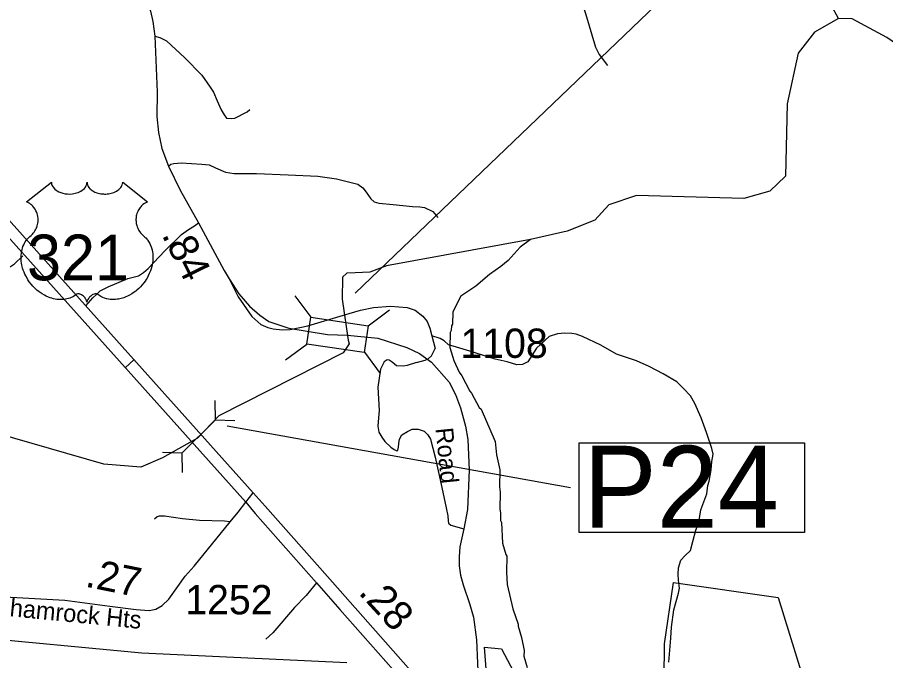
# Model space of a CAD drawing. Extents: x 1159738 to 1321356, y 736314 to 882035.
# Drawn here: x 1275757 to 1279458, y 760767 to 763510 of the extents above; entities that cross this region are included whole.
import ezdxf

# ---------------------------------------------------------------- set-up
doc = ezdxf.new("R2010")
doc.units = 0
for name, color, linetype in [('Exist Boundary Political City Limit New', 7, 'Continuous'), ('Exist Hydrographic Creek Single Shore', 7, 'Continuous'), ('Exist Hydrographic Misc Water Feature', 7, 'Continuous'), ('Exist Road Non-System Type 51', 7, 'Continuous'), ('Exist Road Primary US Divided Attributed', 7, 'Continuous'), ('Exist Road Primary US Mileage Hundredths English Label', 7, 'Continuous'), ('Exist Road Primary US Shield CELL', 7, 'Continuous'), ('Exist Road Primary US Shield Number Label', 7, 'Continuous'), ('Exist Road Primary US Structure Pipe CELL', 7, 'Continuous'), ('Exist Road Primary US Structure Pipe Number Label', 7, 'Continuous'), ('Exist Road Secondary Mileage Hundredths English Label', 7, 'Continuous'), ('Exist Road Secondary Structure Standard Bridge CELL', 7, 'Continuous'), ('Exist Road Secondary Structure Standard Bridge Number Label', 7, 'Continuous'), ('Exist Road Secondary Type 51 Attributed', 7, 'Continuous'), ('Exist Road Secondary Type 51 Label', 7, 'Continuous'), ('Exist Road Secondary Type 51 Number Label', 7, 'Continuous'), ('Map Preparation Boundary City Limit Buffer Line', 7, 'Continuous')]:
    doc.layers.add(name, color=color, linetype=linetype)

msp = doc.modelspace()

# ---------------------------------------------------------------- linework, layer by layer
at = {"layer": 'Exist Boundary Political City Limit New'}
for points in [[(1278511.7, 760540.3), (1278515.7, 760839), (1278554.1, 761100.2), (1278999.4, 761036.8), (1279308.4, 760038.1)], [(1275619.3, 760456.4), (1275534.8, 760871.3), (1276287.6, 760801.1), (1277161.7, 760759.7)], [(1277763.7, 760620.9), (1277747.9, 760824.6), (1277820.8, 760816.9), (1277947.5, 760578.7)]]:
    msp.add_lwpolyline(points, dxfattribs=at)
at = {"layer": 'Exist Hydrographic Creek Single Shore'}
for points in [[(1279256.7, 763505), (1279224.7, 763564.7), (1278896.6, 763787.9), (1278758.6, 763958.1), (1278294.7, 764394.2), (1278259.6, 764444.5), (1278162.6, 764455.9), (1277896.7, 764497.4), (1277500.6, 764682.6), (1277293.6, 764729.4), (1277035.7, 764741.1), (1276514.6, 764912.5), (1276316.7, 765028), (1275935.6, 765462.4), (1275671.6, 765894.4), (1275435.5, 766142.1), (1275229.6, 766238.2), (1275030.6, 766275)], [(1279256.7, 763505), (1279154.7, 763447.9), (1279085.7, 763357.4), (1279038.6, 763141.7), (1279031.6, 762833.3), (1278963.7, 762769), (1278853.7, 762738.3), (1278395.7, 762750.8), (1278277.7, 762710.6), (1278217.7, 762646.1), (1278100.7, 762599.2), (1277943.5, 762563.4), (1277329.6, 762450.6), (1277258.9, 762423.5), (1277196.4, 762421.4), (1277161.3, 762420), (1277143, 762402.4), (1277140.9, 762308.3), (1277166.7, 762134.1)], [(1280098.6, 762815.2), (1280048.7, 762832.6), (1279945.7, 763038.2), (1279815.7, 763181.9), (1279462.7, 763425.3), (1279314.6, 763503.8), (1279256.7, 763505)], [(1276523.9, 761715.6), (1276375.7, 761632.7), (1276282.6, 761591.9), (1276124.6, 761604.9), (1275586.7, 761760.1), (1275554.7, 761826.4), (1275516.6, 762329.5), (1275469.7, 762455.1), (1275027.6, 762756.1), (1274952.6, 762783.9), (1274794.8, 762745.5), (1274683.6, 762681), (1274528.6, 762487.1), (1274390.3, 762149.8), (1274352, 762101.2)], [(1277255.4, 762409), (1277255.4, 762409)], [(1277166.7, 762134.1), (1277170.7, 762117.7), (1277145.7, 762080.1), (1276615.3, 761811.9), (1276523.9, 761715.6)]]:
    msp.add_lwpolyline(points, dxfattribs=at)
at = {"layer": 'Exist Hydrographic Misc Water Feature'}
msp.add_lwpolyline([(1277943.5, 762563.4), (1277900.3, 762530.3), (1277848.7, 762473.8), (1277817.9, 762448.7), (1277769, 762414.1), (1277711.6, 762363.8), (1277646.4, 762321.6), (1277612.6, 762254.6), (1277611.1, 762202.7), (1277606.8, 762194.8), (1277606.3, 762174.8), (1277602.1, 762167), (1277600.4, 762103), (1277616.8, 762046.5), (1277639.4, 761997.9), (1277651, 761981.6), (1277685.2, 761916.6), (1277693, 761908.4), (1277725.3, 761846.3), (1277733, 761839.3), (1277793.2, 761701.5), (1277799.7, 761645.4), (1277813.9, 761581), (1277811.9, 761509.1), (1277815.3, 761485), (1277813.2, 761413.1), (1277816.8, 761396.9), (1277815.9, 761365), (1277819.7, 761356.9), (1277825.2, 761268.7), (1277838.9, 761220.1), (1277843.7, 761212.2), (1277841.8, 761144.3), (1277844.4, 761092.2), (1277869.4, 760987.5), (1277891.7, 760922.9), (1277891.5, 760914.9), (1277906.1, 760866.5), (1277916.6, 760810.2), (1277915.9, 760786.2), (1277930.5, 760737.8)], dxfattribs=at)
at = {"layer": 'Exist Road Non-System Type 51'}
for points in [[(1278073.2, 763861), (1278092.8, 763812.1), (1278132, 763674.8), (1278178.3, 763526.7), (1278221.1, 763383.3), (1278237.1, 763352.5), (1278272.8, 763305.2)], [(1276342.1, 763430), (1276364.5, 763424.4), (1276391.9, 763410.3), (1276469.9, 763337.2), (1276543.6, 763263.6), (1276578, 763213), (1276592.8, 763191.9)], [(1276592.8, 763191.9), (1276608.8, 763154.2), (1276625.6, 763115.5), (1276637.6, 763094.4), (1276648.8, 763081), (1276667.8, 763078.9), (1276683.3, 763081), (1276736, 763107.8), (1276747.2, 763116.9)], [(1276400.5, 762875.2), (1276411.3, 762883.9), (1276423.2, 762887.5), (1276454.8, 762890.3), (1276543.4, 762884.7), (1276574.3, 762881.8), (1276601, 762869.2), (1276643.9, 762850.2), (1276681.1, 762844.6), (1276776.7, 762845.3), (1276910.9, 762838.9), (1277037.4, 762832.6), (1277117.2, 762821.4), (1277208.5, 762798.9), (1277229.6, 762784.1), (1277243.7, 762765.1), (1277263.3, 762736.3), (1277277.4, 762723.7), (1277297.1, 762718.7), (1277358.2, 762713.1), (1277440.8, 762703.4), (1277471.7, 762702.7), (1277492.1, 762699.2), (1277527.9, 762682.4), (1277549, 762657)], [(1275429.3, 762666.4), (1275448.3, 762635.4), (1275482.7, 762601.7), (1275519.2, 762570.7), (1275556.5, 762552.5), (1275598.6, 762520.1), (1275635.2, 762487.1), (1275659.1, 762463.1), (1275681.5, 762447), (1275698.4, 762441.3), (1275713.9, 762442.8), (1275727.9, 762448.4), (1275744.8, 762459.6), (1275780.6, 762494.1)], [(1276048.4, 762280), (1276078.6, 762314.5), (1276094.1, 762329.3), (1276110.2, 762344.7), (1276143.3, 762360.9), (1276226.9, 762396.8), (1276273.3, 762408.7), (1276293.6, 762422.1), (1276314.7, 762439.7), (1276385, 762514.2), (1276456.5, 762584.1), (1276486.7, 762605.9), (1276511.3, 762621.3), (1276528.9, 762634.7)], [(1276659.3, 762395.2), (1276698, 762318.6), (1276755.5, 762235.1), (1276794.2, 762201.3), (1276824.4, 762188), (1276847.6, 762181.7), (1276886.2, 762177.4), (1276919.3, 762179.5), (1276994.4, 762195.4), (1277147.2, 762240.8)], [(1277147.2, 762240.8), (1277218.9, 762262.4), (1277275.1, 762273), (1277347.5, 762279.3), (1277417.7, 762273.7), (1277452.6, 762261.9), (1277485, 762236.6), (1277503.2, 762214.1), (1277514.5, 762185.3), (1277523.5, 762153), (1277537.4, 762099)], [(1278534.3, 760760.5), (1278541.6, 760863.3), (1278545.6, 760909.9), (1278555.6, 760984), (1278575.6, 761055.6), (1278579.6, 761076.9), (1278574.9, 761110.9), (1278572.9, 761136.3), (1278574.2, 761163), (1278584.9, 761195), (1278602.9, 761215.2), (1278626.2, 761236.5), (1278635.6, 761275.2), (1278648.9, 761323.2), (1278661.6, 761355.9), (1278670.2, 761410.6), (1278696.2, 761479), (1278700.2, 761513.7), (1278706.2, 761533), (1278713.5, 761580.4), (1278717.5, 761616.4), (1278722.2, 761648.4), (1278716.8, 761671.9), (1278694.8, 761739.9), (1278672.2, 761802.6), (1278644.2, 761863.3), (1278626.2, 761896.7), (1278595.5, 761928), (1278568.2, 761956), (1278509.8, 761991), (1278449.8, 762021.7), (1278395.2, 762045.7), (1278309.9, 762073.7), (1278243.2, 762112.4), (1278165.2, 762149.8), (1278138.8, 762158.9), (1278120.2, 762162.9), (1278090.8, 762164.2), (1278059.5, 762160.2), (1278023.5, 762150.2), (1277970.2, 762099.5), (1277932.4, 762040.9), (1277910.4, 762029.6), (1277885.1, 762028.2), (1277844.4, 762040.9), (1277792.7, 762052.9), (1277685.8, 762086.9), (1277628, 762104.2), (1277594.1, 762113.6), (1277576.1, 762130.9), (1277559.4, 762141.6), (1277523.5, 762153)], [(1277458.3, 762039.2), (1277494.8, 762048), (1277508.2, 762054.2), (1277521.6, 762067.6), (1277537.4, 762099)], [(1276216.5, 762015.3), (1276254.4, 762051.9)], [(1277458.3, 762039.2), (1277417.6, 762026.3), (1277403.1, 762023.2), (1277372.2, 762024.3), (1277353.7, 762039.7), (1277341.3, 762049), (1277333.1, 762050), (1277319.7, 762041.8), (1277304.2, 762010.9), (1277293.2, 761933.9)], [(1277293.2, 761933.9), (1277298.8, 761833.4), (1277296.1, 761803), (1277292.6, 761766.5), (1277297.5, 761741.2), (1277310.1, 761720.1), (1277322.8, 761701.1), (1277348.8, 761677.9), (1277362.8, 761667.3), (1277374.8, 761661.7), (1277379, 761664.5), (1277381.1, 761677.2), (1277382.5, 761692.6), (1277386, 761711.6), (1277395.9, 761729.9), (1277419.1, 761744.7), (1277439.4, 761753.8), (1277465.4, 761753.8), (1277491.4, 761746.1), (1277506.9, 761730.6), (1277517.4, 761711.6), (1277537.8, 761635), (1277565.9, 761504.9), (1277584.7, 761418.7), (1277591, 761384.9), (1277593.1, 761363.1), (1277593.9, 761354), (1277605.1, 761345.5), (1277659.9, 761330)], [(1276663.2, 761359.5), (1276639, 761361.5), (1276533.4, 761365.3), (1276460.7, 761372.1), (1276384.2, 761383.8), (1276361, 761383.8), (1276353.2, 761380.8), (1276341.6, 761370.2)], [(1277031.5, 761099.6), (1277006.2, 761067.9), (1276987.9, 761045.4), (1276938, 760993.4), (1276846, 760886.5), (1276816.4, 760859.1)]]:
    msp.add_lwpolyline(points, dxfattribs=at)
at = {"layer": 'Exist Road Primary US Divided Attributed'}
for points in [[(1276761.9, 761482.7), (1274721, 763763.6), (1274480.5, 764027.9), (1274341.6, 764181.8), (1274336.1, 764187.9), (1274158.2, 764387.1), (1273955.8, 764610.5), (1273937.2, 764629.8), (1273665.3, 764929.8), (1273491.1, 765126.5), (1273244.4, 765402.2), (1272934.1, 765748.5), (1272883, 765805.3), (1272660.8, 766051.7), (1272348.9, 766398.3), (1272213.6, 766549.1), (1272116.1, 766659.4), (1272031.2, 766754.1), (1271838.3, 766967.2), (1271569.7, 767262), (1271493.2, 767352.1), (1271065.1, 767830.6)], [(1271023.6, 767793.5), (1271459.7, 767322.4), (1271535.9, 767232.7), (1271794.5, 766934.6), (1271824.4, 766899.2), (1271959.1, 766752.4), (1272182.4, 766504.4), (1272240.1, 766441.4), (1272337.9, 766331.1), (1273164.5, 765409.1), (1273205.2, 765363.3), (1273370.7, 765181.3), (1273442.3, 765099.1), (1273663.8, 764841.4), (1273741.2, 764755.3), (1273926.3, 764563.6), (1274002.6, 764479.8), (1274119.3, 764350.9), (1274294.4, 764154.2), (1274358, 764082.6), (1274673.3, 763740.4), (1276730.3, 761442.6)], [(1277736.2, 760394.7), (1277655.5, 760474.7), (1277476.4, 760675.6), (1277079.1, 761125.6), (1276813.1, 761426), (1276761.9, 761482.7)], [(1276730.3, 761442.6), (1276770.9, 761394.3), (1277031.5, 761099.6), (1277131.8, 760985.7), (1277392.8, 760689.7), (1277491.2, 760578.6), (1277689.2, 760354.6), (1277747.5, 760296.9)]]:
    msp.add_lwpolyline(points, dxfattribs=at)
at = {"layer": 'Exist Road Primary US Shield CELL'}
msp.add_lwpolyline([(1275901.5, 762807.8), (1275901.7, 762803.4), (1275902.8, 762798.2), (1275903.6, 762795.5), (1275906.1, 762790.4), (1275910.1, 762784.3), (1275915.7, 762778.3), (1275922, 762773.1), (1275926.3, 762770.3), (1275933.6, 762766.4), (1275941.8, 762763), (1275950.9, 762760.3), (1275960.3, 762758.5), (1275970.5, 762757.3), (1275980.6, 762757.1), (1275991.6, 762758), (1276003.6, 762760.3), (1276009.2, 762761.7), (1276015.4, 762763.9), (1276021.2, 762766.2), (1276027.5, 762769.6), (1276032.6, 762772.9), (1276036.6, 762775.8), (1276042.2, 762781.2), (1276046.7, 762786.8), (1276048.6, 762789.9), (1276050.2, 762792.9), (1276052.5, 762799.3), (1276053.1, 762802.2), (1276053.5, 762808.1), (1276053.9, 762803.1), (1276054.4, 762800), (1276055.2, 762797), (1276056.5, 762793.8), (1276058.8, 762789.3), (1276061.3, 762785.5), (1276066, 762779.9), (1276069, 762777.2), (1276071.6, 762775), (1276078.9, 762770), (1276087.3, 762765.7), (1276091.5, 762763.9), (1276095.7, 762762.4), (1276101.1, 762760.8), (1276106.7, 762759.5), (1276112.2, 762758.5), (1276117.9, 762757.7), (1276123.7, 762757.3), (1276128.4, 762757.1), (1276134.1, 762757.2), (1276139.5, 762757.5), (1276144.9, 762758.1), (1276151, 762759.2), (1276155.8, 762760.2), (1276162.2, 762761.9), (1276168, 762764), (1276173.1, 762766.2), (1276179.6, 762769.6), (1276185, 762773), (1276188.9, 762776.1), (1276193.5, 762780.4), (1276197.9, 762785.5), (1276200.5, 762789.2), (1276202.3, 762793), (1276204, 762797), (1276205, 762801.3), (1276205.5, 762805), (1276205.6, 762808.2), (1276311.9, 762723.5), (1276309.4, 762722.5), (1276303.6, 762719.7), (1276299.1, 762717), (1276291.7, 762711.9), (1276288.6, 762709), (1276285.5, 762706.1), (1276282.6, 762702.9), (1276280, 762700), (1276277, 762695.7), (1276274.2, 762691.5), (1276271.5, 762686.7), (1276269.5, 762682.7), (1276266.3, 762674.1), (1276264.7, 762668.7), (1276263.7, 762664.1), (1276262.4, 762654.7), (1276262.1, 762650.1), (1276262.1, 762645.7), (1276262.4, 762641), (1276262.8, 762636.4), (1276263.6, 762631.7), (1276264.4, 762627.6), (1276265.7, 762622.5), (1276267.6, 762616.6), (1276269.9, 762610.9), (1276274.8, 762601.7), (1276281, 762592.2), (1276285.5, 762587), (1276289.9, 762582.4), (1276296.4, 762576.9), (1276300, 762573.8), (1276304, 762569.7), (1276310.7, 762562), (1276313.4, 762558.3), (1276316.1, 762554.2), (1276318.6, 762550), (1276321.1, 762545.5), (1276323.2, 762541.6), (1276326.9, 762532.4), (1276329.6, 762523.6), (1276330.9, 762518.9), (1276332.9, 762508.5), (1276333.6, 762503.4), (1276334.4, 762493.2), (1276334.5, 762480.9), (1276333.5, 762469.2), (1276331.3, 762455.6), (1276329.5, 762447.4), (1276326.7, 762437.9), (1276324, 762429.7), (1276319.1, 762417.6), (1276314.8, 762408.8), (1276309.3, 762398.5), (1276305.4, 762392.3), (1276301, 762385.6), (1276295.4, 762378), (1276288.9, 762369.8), (1276281, 762361.2), (1276274.7, 762354.9), (1276266.4, 762347.4), (1276261.4, 762343.3), (1276254.2, 762337.9), (1276244.4, 762331.4), (1276234.7, 762325.8), (1276226.5, 762321.6), (1276219.2, 762318.4), (1276209.8, 762314.8), (1276194.1, 762310.5), (1276188.4, 762309.3), (1276181.7, 762308.3), (1276175.3, 762307.7), (1276169.2, 762307.3), (1276160.9, 762307.3), (1276152.7, 762307.9), (1276144.9, 762309.1), (1276136.8, 762310.8), (1276128.3, 762313.3), (1276120.6, 762316.3), (1276112.8, 762320.1), (1276099.7, 762328.4), (1276095.9, 762330.4), (1276093.7, 762331), (1276088.7, 762331.2), (1276083.9, 762330.2), (1276079, 762328.3), (1276076, 762326.7), (1276072.1, 762324.1), (1276069.1, 762321.8), (1276065.5, 762318.3), (1276063, 762315.4), (1276061, 762313.2), (1276057.3, 762307.3), (1276056, 762304.5), (1276054.6, 762301), (1276053.4, 762295.7), (1276051.8, 762302.3), (1276049.8, 762306.7), (1276047.5, 762310.5), (1276045.2, 762313.8), (1276041.5, 762318.1), (1276038.2, 762321.3), (1276034.1, 762324.6), (1276029.9, 762327.2), (1276026.5, 762328.9), (1276023.3, 762330.1), (1276019.5, 762331.1), (1276016.4, 762331.3), (1276013.8, 762331.2), (1276010.2, 762330.4), (1276005.4, 762327), (1276000.9, 762323.8), (1275995.9, 762320.8), (1275990, 762317.6), (1275985.7, 762315.6), (1275980.5, 762313.6), (1275974.5, 762311.6), (1275968, 762309.9), (1275961.3, 762308.6), (1275955.4, 762307.6), (1275949, 762307.1), (1275943.3, 762306.9), (1275937.4, 762306.9), (1275931.8, 762307.4), (1275925.3, 762307.9), (1275917.3, 762309.1), (1275910.6, 762310.6), (1275903.6, 762312.5), (1275896.4, 762314.8), (1275888.7, 762317.7), (1275879, 762321.9), (1275872.3, 762325.4), (1275861.7, 762331.5), (1275849.2, 762340.1), (1275839.9, 762347.7), (1275833, 762353.9), (1275822.9, 762364.2), (1275816.9, 762370.9), (1275807.6, 762383), (1275801.7, 762391.7), (1275797.8, 762398.1), (1275792.2, 762408.4), (1275789, 762414.9), (1275785, 762424.3), (1275781.9, 762432.9), (1275779.2, 762441.1), (1275777.8, 762446.3), (1275775.8, 762455.4), (1275774.6, 762461.9), (1275773.4, 762470.7), (1275772.7, 762480.1), (1275772.6, 762488.7), (1275772.8, 762495.8), (1275773.6, 762504.2), (1275775.1, 762513), (1275776.7, 762520.6), (1275778.3, 762526.1), (1275780.5, 762532.8), (1275783.5, 762540.1), (1275787, 762547.1), (1275790.4, 762553), (1275794.6, 762559.3), (1275798.7, 762564.6), (1275804.2, 762570.5), (1275809.8, 762575.9), (1275815, 762580.1), (1275821.2, 762586.1), (1275824.4, 762589.8), (1275828.2, 762594.9), (1275831.3, 762599.6), (1275833.7, 762603.8), (1275837, 762610), (1275838.9, 762614.6), (1275841.4, 762621.8), (1275842.6, 762626.8), (1275843.8, 762633.3), (1275844.7, 762639.4), (1275845, 762647), (1275844.8, 762653.3), (1275844, 762660.6), (1275842.6, 762667.7), (1275840.9, 762673.8), (1275838.3, 762680.8), (1275835.9, 762686), (1275831.8, 762693), (1275827.3, 762699.4), (1275822.6, 762704.7), (1275817.9, 762709.4), (1275813.4, 762712.9), (1275809.1, 762716), (1275803.7, 762719.3), (1275798.5, 762721.8), (1275795.2, 762723.2)], close=True, dxfattribs=at)
at = {"layer": 'Exist Road Primary US Structure Pipe CELL'}
for p, q in [((1276597.9, 761876.2), (1276599.9, 761792.9)), ((1276599.9, 761792.9), (1276459.1, 761653.2)), ((1276683.1, 761790.4), (1276599.9, 761792.9)), ((1276375.9, 761655.7), (1276459.1, 761653.2)), ((1276461.1, 761569.9), (1276459.1, 761653.2))]:
    msp.add_line(p, q, dxfattribs=at)
at = {"layer": 'Exist Road Primary US Structure Pipe Number Label'}
msp.add_line((1276650.8, 761769.1), (1278113.8, 761504.9), dxfattribs=at)
msp.add_lwpolyline([(1278151.2, 761696), (1279112.6, 761696), (1279112.6, 761313.8), (1278151.2, 761313.8)], close=True, dxfattribs=at)
at = {"layer": 'Exist Road Secondary Structure Standard Bridge CELL'}
for p, q in [((1276939.5, 762322.5), (1277007, 762231.7)), ((1277252.2, 762195.1), (1277343, 762262.6)), ((1276899.4, 762049.6), (1276990.2, 762117.1)), ((1277235.7, 762083.1), (1277303.3, 761992.3))]:
    msp.add_line(p, q, dxfattribs=at)
msp.add_lwpolyline([(1277007, 762231.7), (1277252.3, 762195.6), (1277235.4, 762081.1), (1276990.2, 762117.1)], close=True, dxfattribs=at)
at = {"layer": 'Exist Road Secondary Structure Standard Bridge Number Label'}
msp.add_line((1277196.4, 762334.1), (1279217.4, 764271.8), dxfattribs=at)
at = {"layer": 'Exist Road Secondary Type 51 Attributed'}
for points in [[(1276003.2, 764023.1), (1276073.1, 763945.2), (1276160.3, 763850.3), (1276206.4, 763793.1), (1276255.7, 763718.6), (1276290.8, 763645.7), (1276323.6, 763537.2), (1276333.6, 763493.3), (1276342.1, 763430), (1276352.5, 763191.1), (1276351.1, 763088.1), (1276358.2, 763019.9), (1276372.9, 762951), (1276400.5, 762875.2), (1276450.8, 762773), (1276528.9, 762634.7), (1276638.3, 762430.3), (1276659.3, 762395.2)], [(1276660, 762395), (1276701.2, 762331.1), (1276746.6, 762279.5), (1276789.8, 762240.4), (1276829, 762213.6), (1276913.9, 762185.4), (1277078.8, 762157.6), (1277163.5, 762155.6)], [(1277163.5, 762155.6), (1277293.7, 762142.1), (1277416.9, 762102.4), (1277470.5, 762077.6), (1277521.6, 762040.4), (1277596.8, 761954.6), (1277624.5, 761902.2), (1277646, 761845.2)], [(1277646, 761845.2), (1277667, 761767.2), (1277677.4, 761709.6), (1277683, 761580.2), (1277675.4, 761411.6), (1277659.9, 761330), (1277643.3, 761251.9), (1277639.9, 761210.5), (1277640.1, 761171.5), (1277646.1, 761131.5), (1277656.7, 761090.8), (1277683.4, 761010.8), (1277700.4, 760953), (1277714, 760855.9), (1277722, 760657.4), (1277734.1, 760433.3), (1277736.2, 760394.7)], [(1276730.3, 761442.6), (1276761.9, 761482.7)], [(1275457.5, 761013.8), (1275479.9, 761023.2), (1275536.5, 761032.3), (1275584.7, 761038.9), (1275639.9, 761043), (1275728.7, 761037.8), (1275958.5, 761025.3), (1276151.5, 761000.2), (1276262.5, 760985.6), (1276318.8, 760980.9), (1276347.4, 760986.1), (1276374.5, 761002.3), (1276402.2, 761029.4), (1276441.2, 761083.1), (1276472.5, 761127), (1276509.6, 761170), (1276663.2, 761359.5), (1276698, 761401.1), (1276730.3, 761442.6)]]:
    msp.add_lwpolyline(points, dxfattribs=at)
at = {"layer": 'Map Preparation Boundary City Limit Buffer Line'}
for points in [[(1278511.7, 760540.3), (1278515.7, 760839), (1278554.1, 761100.2), (1278999.4, 761036.8), (1279308.4, 760038.1)], [(1275619.3, 760456.4), (1275534.8, 760871.3), (1276287.6, 760801.1), (1277161.7, 760759.7)], [(1277763.7, 760620.9), (1277747.9, 760824.6), (1277820.8, 760816.9), (1277947.5, 760578.7)]]:
    msp.add_lwpolyline(points, dxfattribs=at)

# ---------------------------------------------------------------- texts
at = {"layer": 'Exist Road Primary US Mileage Hundredths English Label'}
msp.add_text('.28', height=125, rotation=312.5177, dxfattribs=at).set_placement((1277207.1, 761055.5))
at = {"layer": 'Exist Road Primary US Shield Number Label'}
msp.add_text('321', height=195, dxfattribs=at).set_placement((1275797.6, 762389.1))
at = {"layer": 'Exist Road Primary US Structure Pipe Number Label'}
msp.add_text('P24', height=350, dxfattribs=at).set_placement((1278169.7, 761333.6))
at = {"layer": 'Exist Road Secondary Mileage Hundredths English Label'}
for s, rotation, p in [('.84', 296.1941, (1276370.7, 762583.3)), ('.27', 348.5333, (1276042.3, 761083.6))]:
    msp.add_text(s, height=125, rotation=rotation, dxfattribs=at).set_placement(p)
at = {"layer": 'Exist Road Secondary Type 51 Label'}
for s, rotation, p in [('Road', 275.7854, (1277538.7, 761757.5)), ('Shamrock Hts', 354.4683, (1275655.2, 760963.4))]:
    msp.add_text(s, height=75, rotation=rotation, dxfattribs=at).set_placement(p)
at = {"layer": 'Exist Road Secondary Type 51 Number Label'}
for s, p in [('1108', (1277645.4, 762058.3)), ('1108', (1277645.4, 762058.3)), ('1108', (1277645.4, 762058.3)), ('1108', (1277645.4, 762058.3)), ('1108', (1277645.4, 762058.3)), ('1108', (1277645.4, 762058.3)), ('1108', (1277645.4, 762058.3)), ('1252', (1276472.5, 760964.8)), ('1252', (1276472.5, 760964.8)), ('1252', (1276472.5, 760964.8)), ('1252', (1276472.5, 760964.8)), ('1252', (1276472.5, 760964.8)), ('1252', (1276472.5, 760964.8)), ('1252', (1276472.5, 760964.8)), ('1252', (1276472.5, 760964.8))]:
    msp.add_text(s, height=125, dxfattribs=at).set_placement(p)

doc.saveas('drawing.dxf')
